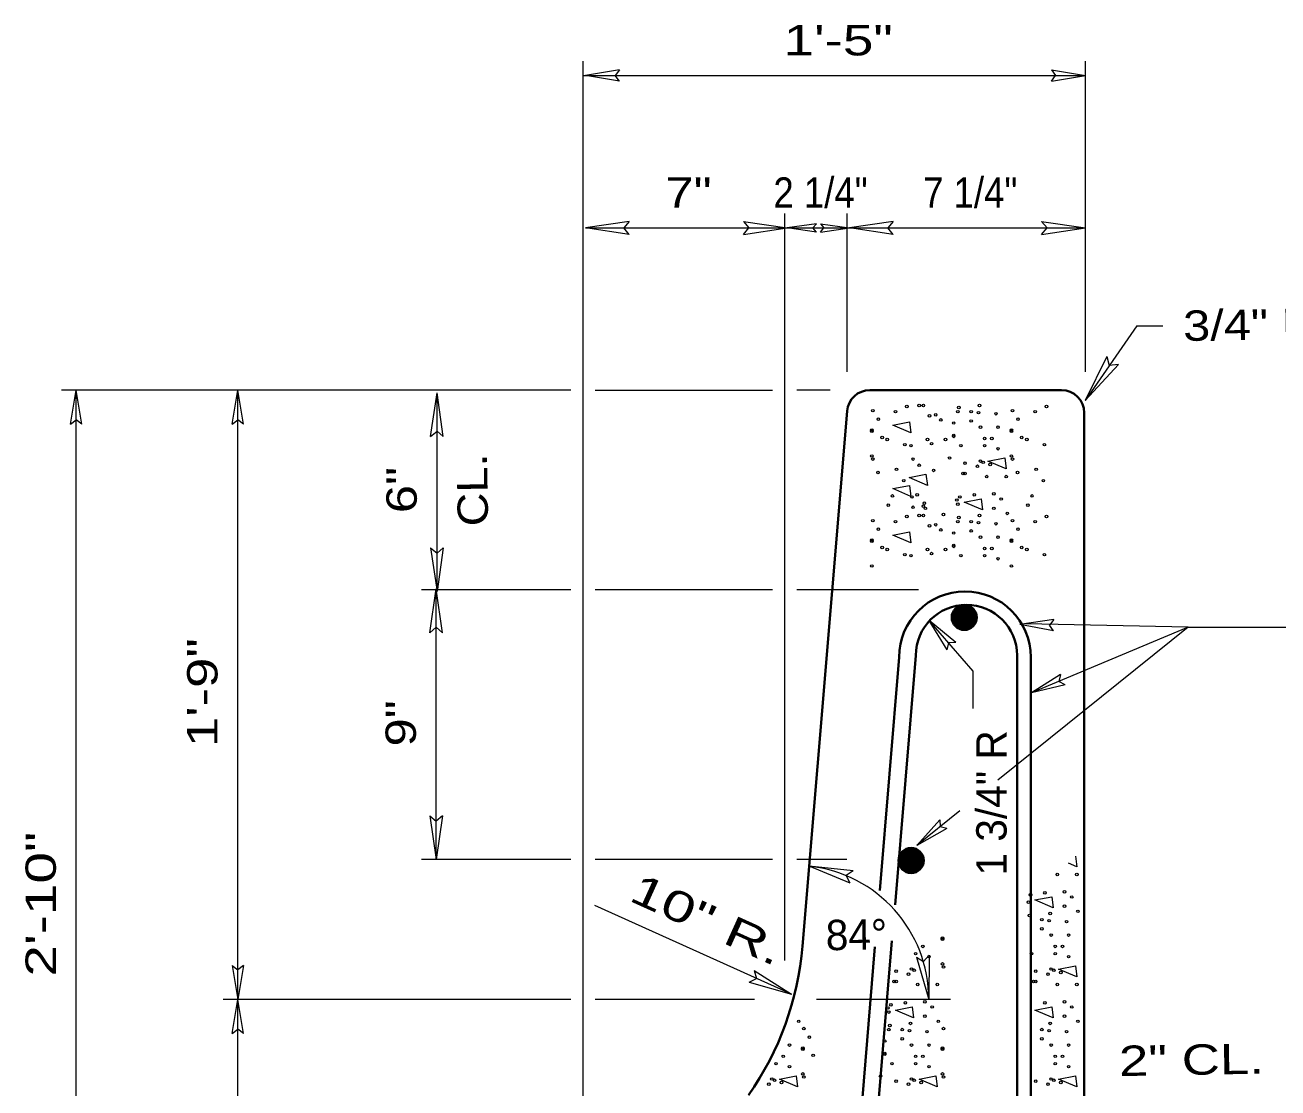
# Model space of a CAD drawing. Extents: x -16.43 to -9.36, y -8.57 to 1.26.
# Drawn here: x -15.379 to -12.904, y -0.843 to 1.258 of the extents above; entities that cross this region are included whole.
import ezdxf
from ezdxf.enums import TextEntityAlignment as Align

# ---------------------------------------------------------------- set-up
doc = ezdxf.new("R2010")
doc.units = 0
doc.header["$LTSCALE"] = 0.024
for name, color, linetype, lineweight in [('1', 7, 'Continuous', 35), ('10', 7, 'Continuous', 13), ('12', 7, 'Continuous', 53), ('6', 7, 'Continuous', 13)]:
    doc.layers.add(name, color=color, linetype=linetype, lineweight=lineweight)

msp = doc.modelspace()

# ---------------------------------------------------------------- linework, layer by layer
at = {"layer": '1'}
for p, q in [((-13.33133, 0.53633), (-13.71, 0.53633)), ((-13.75483, 0.495), (-13.843, -0.56233)), ((-13.28633, 0.49133), (-13.28633, -1.504)), ((-13.652, 0.00867), (-13.69033, -0.45217)), ((-13.61917, 0.01217), (-13.66017, -0.4805)), ((-13.392, 0.00867), (-13.392, -2.83033)), ((-13.69975, -0.56375), (-13.88817, -2.82583)), ((-13.66625, -0.552), (-13.85583, -2.82733))]:
    msp.add_line(p, q, dxfattribs=at)
msp.add_lwpolyline([(-13.41917, 0.01217), (-13.41917, -2.83033), (-13.392, -2.83033)], dxfattribs=at)
for centre, radius in [((-13.52337, 0.08721), 0.02478), ((-13.52357, 0.087), 0.02313), ((-13.52299, 0.08727), 0.0223), ((-13.52194, 0.08793), 0.02187), ((-13.52357, 0.08477), 0.02005), ((-13.52272, 0.08781), 0.02035), ((-13.5226, 0.08836), 0.01926), ((-13.52455, 0.08559), 0.01659), ((-13.52205, 0.08852), 0.01826), ((-13.52178, 0.08879), 0.01742), ((-13.52135, 0.08852), 0.01661), ((-13.52135, 0.08894), 0.01618), ((-13.52163, 0.08863), 0.01563), ((-13.5226, 0.0852), 0.0144), ((-13.52124, 0.08933), 0.01494), ((-13.52151, 0.08949), 0.014), ((-13.52166, 0.08961), 0.01302), ((-13.52194, 0.08961), 0.01193), ((-13.52163, 0.08976), 0.01123), ((-13.52151, 0.08976), 0.01014), ((-13.52065, 0.09019), 0.00971), ((-13.52053, 0.09043), 0.00885), ((-13.52178, 0.08395), 0.0115), ((-13.52233, 0.08586), 0.00929), ((-13.52077, 0.09043), 0.00776), ((-13.52096, 0.09074), 0.0075), ((-13.52081, 0.09101), 0.00663), ((-13.52026, 0.09074), 0.0069), ((-13.52065, 0.09113), 0.00567), ((-13.52108, 0.09074), 0.00473), ((-13.5205, 0.09128), 0.00421), ((-13.52053, 0.09144), 0.00348), ((-13.52053, 0.09253), 0.00294), ((-13.52038, 0.09171), 0.00265), ((-13.52065, 0.09171), 0.00234), ((-13.52065, 0.09167), 0.00153), ((-13.52065, 0.0914), 0.000719), ((-13.52065, 0.09198), 0.000456), ((-13.62834, -0.39319), 0.02478), ((-13.62855, -0.3934), 0.02313), ((-13.62797, -0.39313), 0.0223), ((-13.62691, -0.39247), 0.02187), ((-13.62855, -0.39562), 0.02005), ((-13.62769, -0.39258), 0.02035), ((-13.62758, -0.39204), 0.01926), ((-13.62953, -0.39481), 0.01659), ((-13.62703, -0.39188), 0.01826), ((-13.62676, -0.39161), 0.01742), ((-13.62633, -0.39188), 0.01661), ((-13.62633, -0.39145), 0.01618), ((-13.6266, -0.39176), 0.01563), ((-13.62758, -0.39519), 0.0144), ((-13.62621, -0.39106), 0.01494), ((-13.62649, -0.39091), 0.014), ((-13.62664, -0.39079), 0.01302), ((-13.62691, -0.39079), 0.01193), ((-13.62676, -0.39644), 0.0115), ((-13.6266, -0.39063), 0.01123), ((-13.62649, -0.39063), 0.01014), ((-13.6273, -0.39453), 0.00929), ((-13.62563, -0.39021), 0.00971), ((-13.62551, -0.38997), 0.00885), ((-13.62575, -0.38997), 0.00776), ((-13.62594, -0.38966), 0.0075), ((-13.62578, -0.38939), 0.00663), ((-13.62524, -0.38966), 0.0069), ((-13.62563, -0.38927), 0.00567), ((-13.62606, -0.38966), 0.00473), ((-13.62547, -0.38911), 0.00421), ((-13.62551, -0.38896), 0.00348), ((-13.62551, -0.38787), 0.00294), ((-13.62536, -0.38869), 0.00265), ((-13.62563, -0.38869), 0.00234), ((-13.62563, -0.38872), 0.00153), ((-13.62563, -0.389), 0.000719), ((-13.62563, -0.38841), 0.000456)]:
    msp.add_circle(centre, radius, dxfattribs=at)
for centre, radius, start, end in [((-13.71003, 0.49135), 0.04501, 90, 175.23532), ((-13.33137, 0.49135), 0.04501, 0, 90), ((-13.522, 0.00859), 0.12998, 0, 180), ((-13.51912, 0.01211), 0.10002, 0, 180), ((-14.44102, -0.51249), 0.6001, 325.00798, 355.23636)]:
    msp.add_arc(centre, radius, start, end, dxfattribs=at)
at = {"layer": '10'}
for p, q in [((-14.2765, -0.49767), (-14.2765, 1.18667)), ((-14.2045, 1.169), (-14.27167, 1.15783)), ((-14.2045, 1.169), (-14.21283, 1.15783)), ((-13.35133, 1.169), (-13.28417, 1.15783)), ((-13.35133, 1.169), (-13.343, 1.15783)), ((-13.28417, 0.5725), (-13.28417, 1.18667)), ((-14.2765, 1.15783), (-13.28417, 1.15783)), ((-14.2045, 1.14667), (-14.27167, 1.15783)), ((-14.2045, 1.14667), (-14.21283, 1.15783)), ((-13.35133, 1.14667), (-13.28417, 1.15783)), ((-13.35133, 1.14667), (-13.343, 1.15783)), ((-14.18533, 0.86933), (-14.27167, 0.85683)), ((-14.18533, 0.86933), (-14.196, 0.85683)), ((-13.9595, 0.86933), (-13.87317, 0.85683)), ((-13.9595, 0.86933), (-13.94867, 0.85683)), ((-13.878, -0.43817), (-13.878, 0.88567)), ((-13.75483, 0.5725), (-13.75483, 0.88567)), ((-13.66367, 0.86933), (-13.75, 0.85683)), ((-13.66367, 0.86933), (-13.6745, 0.85683)), ((-13.3705, 0.86933), (-13.28417, 0.85683)), ((-13.3705, 0.86933), (-13.35983, 0.85683)), ((-14.18533, 0.84417), (-14.27167, 0.85683)), ((-14.18533, 0.84417), (-14.196, 0.85683)), ((-13.9595, 0.84417), (-13.87317, 0.85683)), ((-13.9595, 0.84417), (-13.94867, 0.85683)), ((-13.8155, 0.86517), (-13.87317, 0.85683)), ((-13.8155, 0.84833), (-13.87317, 0.85683)), ((-13.8155, 0.86517), (-13.82267, 0.85683)), ((-13.8155, 0.84833), (-13.82267, 0.85683)), ((-13.80767, 0.86517), (-13.75, 0.85683)), ((-13.80767, 0.86517), (-13.8005, 0.85683)), ((-13.80767, 0.84833), (-13.75, 0.85683)), ((-13.80767, 0.84833), (-13.8005, 0.85683)), ((-13.66367, 0.84417), (-13.75, 0.85683)), ((-13.66367, 0.84417), (-13.6745, 0.85683)), ((-13.3705, 0.84417), (-13.28417, 0.85683)), ((-13.3705, 0.84417), (-13.35983, 0.85683)), ((-13.1825, 0.6635), (-13.28483, 0.51583)), ((-13.1825, 0.6635), (-13.13117, 0.6635)), ((-13.24167, 0.60267), (-13.28483, 0.51583)), ((-13.24167, 0.60267), (-13.23683, 0.58483)), ((-13.21867, 0.58667), (-13.28483, 0.51583)), ((-13.21867, 0.58667), (-13.23683, 0.58483)), ((-14.3005, 0.53633), (-15.30683, 0.53633)), ((-15.28917, 0.46917), (-15.278, 0.53633)), ((-15.278, -1.504), (-15.278, 0.53633)), ((-15.26683, 0.46917), (-15.278, 0.53633)), ((-14.96983, 0.46917), (-14.95867, 0.53633)), ((-14.9475, 0.46917), (-14.95867, 0.53633)), ((-14.57767, 0.44467), (-14.565, 0.53117)), ((-14.565, 0.13833), (-14.565, 0.53117)), ((-14.5525, 0.44467), (-14.565, 0.53117)), ((-14.2525, 0.53633), (-13.902, 0.53633)), ((-13.7885, 0.53633), (-13.854, 0.53633)), ((-15.28917, 0.46917), (-15.278, 0.4775)), ((-15.26683, 0.46917), (-15.278, 0.4775)), ((-14.96983, 0.46917), (-14.95867, 0.4775)), ((-14.9475, 0.46917), (-14.95867, 0.4775)), ((-14.57767, 0.44467), (-14.565, 0.4555)), ((-14.5525, 0.44467), (-14.565, 0.4555)), ((-14.57767, 0.22467), (-14.565, 0.13833)), ((-14.57767, 0.22467), (-14.565, 0.21383)), ((-14.5525, 0.22467), (-14.565, 0.13833)), ((-14.5525, 0.22467), (-14.565, 0.21383)), ((-14.5955, 0.14217), (-14.3005, 0.14217)), ((-14.57933, 0.057), (-14.56667, 0.1435)), ((-14.55417, 0.057), (-14.56667, 0.1435)), ((-14.56667, -0.39117), (-14.56667, 0.13833)), ((-14.2525, 0.14217), (-13.902, 0.14217)), ((-13.854, 0.14217), (-13.61383, 0.14217)), ((-13.55717, 0.023), (-13.59267, 0.08117)), ((-13.54017, 0.03767), (-13.59267, 0.08117)), ((-13.34633, 0.08283), (-13.41367, 0.073)), ((-13.08117, 0.06817), (-13.4025, 0.0745)), ((-13.34633, 0.08283), (-13.355, 0.07183)), ((-14.57933, 0.057), (-14.56667, 0.06783)), ((-14.55417, 0.057), (-14.56667, 0.06783)), ((-13.08117, 0.06817), (-13.45692, -0.23467)), ((-13.34683, 0.0605), (-13.41367, 0.073)), ((-13.08117, 0.06817), (-13.39067, -0.06217)), ((-13.34683, 0.0605), (-13.355, 0.07183)), ((-13.08117, 0.06817), (-12.78867, 0.06817)), ((-13.55717, 0.023), (-13.55417, 0.03667)), ((-13.54017, 0.03767), (-13.55417, 0.03667)), ((-13.333, -0.02567), (-13.39067, -0.06217)), ((-13.32433, -0.04633), (-13.39067, -0.06217)), ((-13.333, -0.02567), (-13.33633, -0.03933)), ((-13.32433, -0.04633), (-13.33633, -0.03933)), ((-13.53225, -0.29533), (-13.61683, -0.3635)), ((-14.57933, -0.30467), (-14.56667, -0.39117)), ((-14.57933, -0.30467), (-14.56667, -0.3155)), ((-14.55417, -0.30467), (-14.56667, -0.39117)), ((-14.55417, -0.30467), (-14.56667, -0.3155)), ((-13.57167, -0.31267), (-13.61683, -0.3635)), ((-13.57167, -0.31267), (-13.57117, -0.32667)), ((-13.5575, -0.33), (-13.61683, -0.3635)), ((-13.5575, -0.33), (-13.57117, -0.32667)), ((-14.3005, -0.39117), (-14.5955, -0.39117)), ((-13.902, -0.39117), (-14.2525, -0.39117)), ((-13.75533, -0.39117), (-13.854, -0.39117)), ((-13.749, -0.43767), (-13.82983, -0.4045)), ((-13.743, -0.41333), (-13.82983, -0.4045)), ((-13.743, -0.41333), (-13.7565, -0.42283)), ((-13.878, -0.591), (-13.878, -0.43817)), ((-13.749, -0.43767), (-13.7565, -0.42283)), ((-13.8645, -0.6575), (-14.2535, -0.482)), ((-14.2765, -1.276), (-14.2765, -0.49767)), ((-13.61783, -0.584), (-13.59333, -0.66783)), ((-13.61783, -0.584), (-13.604, -0.59283)), ((-13.593, -0.5805), (-13.604, -0.59283)), ((-13.593, -0.5805), (-13.59333, -0.66783)), ((-14.96983, -0.60067), (-14.95867, -0.66783)), ((-14.96983, -0.60067), (-14.95867, -0.609)), ((-14.9475, -0.60067), (-14.95867, -0.66783)), ((-14.9475, -0.60067), (-14.95867, -0.609)), ((-13.93817, -0.6105), (-13.8645, -0.6575)), ((-13.93817, -0.6105), (-13.9335, -0.62633)), ((-13.9485, -0.63333), (-13.9335, -0.62633)), ((-13.9485, -0.63333), (-13.8645, -0.6575)), ((-14.3005, -0.66783), (-14.9875, -0.66783)), ((-14.96983, -0.735), (-14.95867, -0.66783)), ((-14.9475, -0.735), (-14.95867, -0.66783)), ((-13.938, -0.66783), (-14.2525, -0.66783)), ((-13.55033, -0.66783), (-13.815, -0.66783)), ((-14.96983, -0.735), (-14.95867, -0.72667)), ((-14.9475, -0.735), (-14.95867, -0.72667))]:
    msp.add_line(p, q, dxfattribs=at)
for points in [[(-14.27167, 0.85683), (-13.87317, 0.85683), (-13.75, 0.85683), (-13.28417, 0.85683)], [(-14.95867, -1.504), (-14.95867, -1.324), (-14.95867, -0.66783), (-14.95867, 0.53633)], [(-13.506, -0.0925), (-13.506, -0.01883), (-13.59267, 0.08117)]]:
    msp.add_lwpolyline(points, dxfattribs=at)
msp.add_arc((-13.85816, -0.66778), 0.26476, 0, 83.86453, dxfattribs=at)
at = {"layer": '6'}
for points in [[(-13.66467, 0.46733), (-13.63167, 0.47383), (-13.62867, 0.452)], [(-13.4765, 0.39617), (-13.44333, 0.40267), (-13.4405, 0.38067)], [(-13.66467, 0.34167), (-13.63167, 0.34817), (-13.62867, 0.32617)], [(-13.63217, 0.3635), (-13.599, 0.37), (-13.59617, 0.34817)], [(-13.52333, 0.31517), (-13.49017, 0.32167), (-13.48733, 0.29983)], [(-13.66467, 0.25), (-13.63167, 0.2565), (-13.62867, 0.23467)], [(-13.38367, -0.47117), (-13.35067, -0.46483), (-13.34783, -0.48667)], [(-13.337, -0.60767), (-13.30383, -0.60117), (-13.301, -0.623)], [(-13.6595, -0.68867), (-13.6265, -0.68217), (-13.6235, -0.704)], [(-13.38367, -0.68867), (-13.35067, -0.68217), (-13.34783, -0.704)], [(-13.8885, -0.825), (-13.8555, -0.8185), (-13.8525, -0.84033)], [(-13.61267, -0.825), (-13.57967, -0.8185), (-13.57683, -0.84033)], [(-13.337, -0.825), (-13.30383, -0.8185), (-13.301, -0.84033)]]:
    msp.add_lwpolyline(points, close=True, dxfattribs=at)
msp.add_lwpolyline([(-13.30383, -0.38467), (-13.301, -0.40567), (-13.31767, -0.3985)], dxfattribs=at)
for centre in [(-13.70399, 0.49579), (-13.65918, 0.49375), (-13.63678, 0.50391), (-13.61238, 0.50595), (-13.60421, 0.50595), (-13.53608, 0.49375), (-13.53404, 0.50187), (-13.5096, 0.49375), (-13.49332, 0.50595), (-13.42819, 0.49579), (-13.38338, 0.49375), (-13.36098, 0.50391), (-13.69307, 0.47887), (-13.59201, 0.48559), (-13.57977, 0.48763), (-13.56961, 0.47747), (-13.5442, 0.47135), (-13.5096, 0.47543), (-13.49536, 0.49171), (-13.46075, 0.48967), (-13.41726, 0.47887), (-13.70599, 0.45711), (-13.70599, 0.45507), (-13.5442, 0.4469), (-13.5442, 0.44486), (-13.49128, 0.46319), (-13.45667, 0.46319), (-13.43019, 0.45711), (-13.43019, 0.45507), (-13.68567, 0.44282), (-13.67547, 0.43878), (-13.64086, 0.42858), (-13.62866, 0.42654), (-13.59605, 0.43878), (-13.58793, 0.43062), (-13.56049, 0.43878), (-13.52996, 0.42654), (-13.48315, 0.44082), (-13.48315, 0.42654), (-13.46887, 0.44082), (-13.45667, 0.42046), (-13.40986, 0.44282), (-13.39966, 0.43878), (-13.36506, 0.42858), (-13.70599, 0.40618), (-13.70399, 0.4001), (-13.62458, 0.4001), (-13.55237, 0.40214), (-13.49152, 0.3961), (-13.48588, 0.39366), (-13.43019, 0.40618), (-13.42819, 0.4001), (-13.69379, 0.37361), (-13.65714, 0.37973), (-13.61238, 0.38785), (-13.58385, 0.37769), (-13.52588, 0.37157), (-13.52184, 0.39194), (-13.52184, 0.37157), (-13.4974, 0.38585), (-13.47223, 0.38929), (-13.41798, 0.37361), (-13.38134, 0.37973), (-13.6429, 0.35733), (-13.47907, 0.36549), (-13.44039, 0.36549), (-13.3671, 0.35733), (-13.6653, 0.32728), (-13.62662, 0.32524), (-13.61642, 0.32933), (-13.532, 0.32524), (-13.50352, 0.32933), (-13.46483, 0.33137), (-13.45055, 0.32116), (-13.3895, 0.32728), (-13.67343, 0.30896), (-13.62458, 0.30488), (-13.60421, 0.30692), (-13.60217, 0.31304), (-13.60013, 0.30284), (-13.53812, 0.31912), (-13.53608, 0.311), (-13.46483, 0.30284), (-13.39762, 0.30896), (-13.70399, 0.27844), (-13.65918, 0.2764), (-13.63678, 0.28656), (-13.61238, 0.2886), (-13.60421, 0.2886), (-13.57977, 0.27028), (-13.56457, 0.29064), (-13.53608, 0.2764), (-13.53404, 0.28452), (-13.5096, 0.2764), (-13.49536, 0.27436), (-13.49332, 0.2886), (-13.46075, 0.27232), (-13.43835, 0.29268), (-13.42819, 0.27844), (-13.38338, 0.2764), (-13.36098, 0.28656), (-13.69307, 0.26151), (-13.59201, 0.26824), (-13.56961, 0.26011), (-13.5442, 0.25399), (-13.5096, 0.25807), (-13.49128, 0.24583), (-13.45667, 0.24583), (-13.41726, 0.26151), (-13.70599, 0.23975), (-13.70599, 0.23771), (-13.68567, 0.22547), (-13.67547, 0.22143), (-13.59605, 0.22143), (-13.56049, 0.22143), (-13.5442, 0.22955), (-13.5442, 0.22751), (-13.48315, 0.22347), (-13.46887, 0.22347), (-13.43019, 0.23975), (-13.43019, 0.23771), (-13.40986, 0.22547), (-13.39966, 0.22143), (-13.64086, 0.21123), (-13.62866, 0.20919), (-13.58793, 0.21327), (-13.52996, 0.20919), (-13.48315, 0.20919), (-13.45667, 0.2031), (-13.36506, 0.21123), (-13.70599, 0.18882), (-13.43019, 0.18882), (-13.33953, -0.42091), (-13.30085, -0.42091), (-13.39246, -0.46116), (-13.36398, -0.45708), (-13.32529, -0.45504), (-13.31101, -0.46524), (-13.39654, -0.4754), (-13.32529, -0.48356), (-13.29881, -0.49373), (-13.3945, -0.50189), (-13.37006, -0.51001), (-13.35581, -0.51205), (-13.35377, -0.49781), (-13.32121, -0.51409), (-13.56645, -0.54666), (-13.37006, -0.52833), (-13.35173, -0.54057), (-13.31713, -0.54057), (-13.60513, -0.56294), (-13.56645, -0.5487), (-13.34361, -0.56294), (-13.32933, -0.56294), (-13.61942, -0.57722), (-13.59293, -0.5833), (-13.39042, -0.57722), (-13.34361, -0.57722), (-13.31713, -0.5833), (-13.6581, -0.61183), (-13.63366, -0.61791), (-13.62778, -0.60766), (-13.62214, -0.61011), (-13.56645, -0.59758), (-13.56445, -0.60366), (-13.3823, -0.61183), (-13.35785, -0.61791), (-13.35197, -0.60766), (-13.34633, -0.61011), (-13.33269, -0.61447), (-13.66214, -0.63219), (-13.6581, -0.63219), (-13.61534, -0.63827), (-13.57665, -0.63827), (-13.38634, -0.63219), (-13.3823, -0.63219), (-13.33953, -0.63827), (-13.30085, -0.63827), (-13.67439, -0.68464), (-13.67234, -0.69276), (-13.66826, -0.67852), (-13.63978, -0.67444), (-13.60109, -0.6724), (-13.58681, -0.6826), (-13.36398, -0.67444), (-13.32529, -0.6724), (-13.31101, -0.6826), (-13.85041, -0.71108), (-13.6703, -0.71924), (-13.62958, -0.71516), (-13.60109, -0.70092), (-13.57461, -0.71108), (-13.35377, -0.71516), (-13.32529, -0.70092), (-13.29881, -0.71108), (-13.84025, -0.72532), (-13.82933, -0.74225), (-13.67234, -0.72736), (-13.64586, -0.72736), (-13.63162, -0.7294), (-13.59701, -0.73144), (-13.56445, -0.72532), (-13.37006, -0.72736), (-13.35581, -0.7294), (-13.32121, -0.73144), (-13.86874, -0.75793), (-13.84225, -0.76401), (-13.84225, -0.76605), (-13.68047, -0.74977), (-13.64586, -0.74569), (-13.62754, -0.75793), (-13.59293, -0.75793), (-13.56645, -0.76401), (-13.56645, -0.76605), (-13.37006, -0.74569), (-13.35173, -0.75793), (-13.31713, -0.75793), (-13.88094, -0.78029), (-13.82193, -0.77829), (-13.68047, -0.77421), (-13.68047, -0.77625), (-13.61942, -0.78029), (-13.60513, -0.78029), (-13.34361, -0.78029), (-13.32933, -0.78029), (-13.89522, -0.79457), (-13.86874, -0.80066), (-13.84225, -0.81494), (-13.68863, -0.81898), (-13.66622, -0.79457), (-13.61942, -0.79457), (-13.59293, -0.80066), (-13.56645, -0.81494), (-13.34361, -0.79457), (-13.31713, -0.80066), (-13.90946, -0.83526), (-13.90358, -0.82502), (-13.89794, -0.82746), (-13.8843, -0.83182), (-13.84025, -0.82102), (-13.6581, -0.82918), (-13.63366, -0.83526), (-13.62778, -0.82502), (-13.62214, -0.82746), (-13.60849, -0.83182), (-13.56445, -0.82102), (-13.3823, -0.82918), (-13.35785, -0.83526), (-13.35197, -0.82502), (-13.34633, -0.82746), (-13.33269, -0.83182)]:
    msp.add_circle(centre, 0.00252, dxfattribs=at)

# ---------------------------------------------------------------- texts
at = {"layer": '12'}
for s, width, p in [('1\'-5"', 1.35, (-13.77233, 1.19775)), ('7"', 1.25, (-14.06808, 0.89675)), ('2 1/4"', 0.9, (-13.80729, 0.89675)), ('7 1/4"', 0.9, (-13.51154, 0.89675))]:
    msp.add_text(s, height=0.06001, dxfattribs=dict(at, width=width)).set_placement(p, align=Align.CENTER)
at = {"layer": '12', "width": 1.2}
msp.add_text('3/4" R. TYP.', height=0.06001, rotation=1, dxfattribs=at).set_placement((-13.0905, 0.63342))
at = {"layer": '12'}
for s, rotation, width, p in [('CL.', 91, 1.15, (-14.46509, 0.33943)), ('6"', 90, 1.25, (-14.605, 0.33887)), ('1\'-9"', 90, 1.35, (-14.99867, -0.06154)), ('9"', 90, 1.25, (-14.60667, -0.12221)), ('2\'-10"', 90, 1.4, (-15.31792, -0.47958)), ('10" R.', 335.723, 1.45, (-14.04275, -0.53714)), ('2" CL.', 1, 1.3, (-13.07407, -0.81684))]:
    msp.add_text(s, height=0.06001, rotation=rotation, dxfattribs=dict(at, width=width)).set_placement(p, align=Align.CENTER)
msp.add_text('1 3/4" R', height=0.06001, rotation=90, dxfattribs=at).set_placement((-13.43975, -0.13575), align=Align.RIGHT)
msp.add_text('84°', height=0.06001, rotation=1, dxfattribs=at).set_placement((-13.73586, -0.56965), align=Align.CENTER)

doc.saveas('drawing.dxf')
